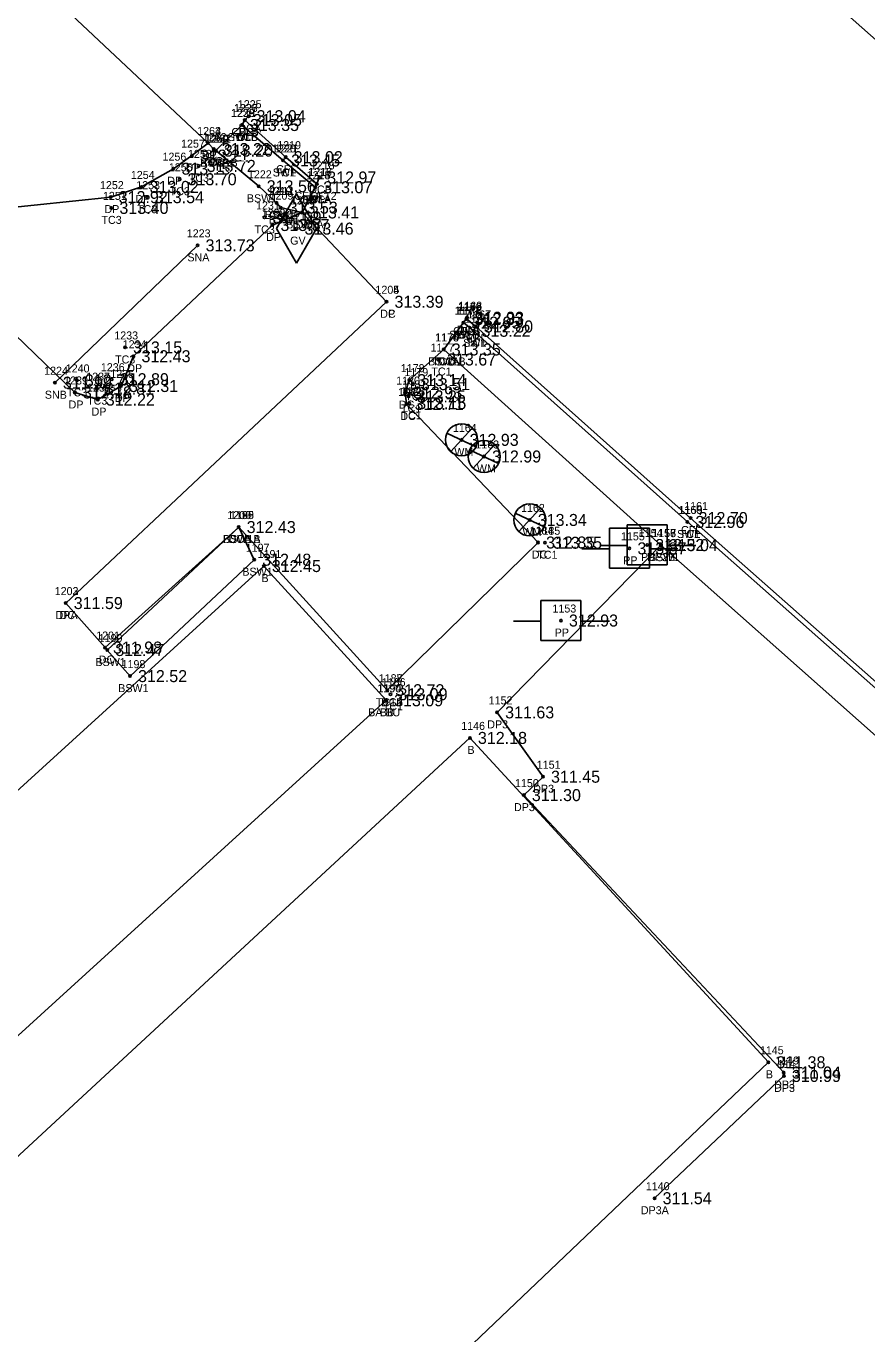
# Model space of a CAD drawing. Extents: x 1970076 to 1971136, y 803126 to 804215.
# Drawn here: x 1970736.9 to 1970842, y 803214.9 to 803378.3 of the extents above; entities that cross this region are included whole.
import ezdxf

# ---------------------------------------------------------------- set-up
doc = ezdxf.new("R2010")
doc.units = 0
for name, color, linetype in [('RD_EX_Bldg', 7, 'Continuous'), ('RD_EX_Bldg_txCode', 7, 'Continuous'), ('RD_EX_BldgApp', 7, 'Continuous'), ('RD_EX_BldgApp_txCode', 7, 'Continuous'), ('RD_EX_Conc', 7, 'Continuous'), ('RD_EX_Conc_txCode', 7, 'Continuous'), ('RD_EX_DR_Pipe', 7, 'Continuous'), ('RD_EX_Driveway', 7, 'Continuous'), ('RD_EX_Driveway_txCode', 7, 'Continuous'), ('RD_EX_TX_Bldg_ELEV', 7, 'Continuous'), ('RD_EX_TX_BldgApp_ELEV', 7, 'Continuous'), ('RD_EX_TX_Conc_ELEV', 7, 'Continuous'), ('RD_EX_TX_Driveway_ELEV', 7, 'Continuous'), ('RD_EX_TX_UT_ELEV', 7, 'Continuous'), ('RD_EX_UT', 7, 'Continuous'), ('RD_EX_UT_txCode', 7, 'Continuous'), ('RD_HC_Survey_ELEV', 7, 'Continuous'), ('RD_SMD_Locator', 7, 'Continuous')]:
    doc.layers.add(name, color=color, linetype=linetype)

msp = doc.modelspace()

# ---------------------------------------------------------------- linework, layer by layer
at = {"layer": 'RD_EX_Bldg'}
for points in [[(1970781.9, 803294.06), (1970766.62, 803310.84), (1970707.47, 803256.98), (1970722.75, 803240.2), (1970781.9, 803294.06)], [(1970698.2, 803132.22), (1970763.48, 803192.62), (1970767.27, 803189.39), (1970829.69, 803248.82), (1970792.38, 803289.36), (1970663.41, 803170.02), (1970698.2, 803132.22)]]:
    msp.add_lwpolyline(points, dxfattribs=at)
at = {"layer": 'RD_EX_BldgApp'}
msp.add_line((1970758.33, 803350.92), (1970740.49, 803333.75), dxfattribs=at)
at = {"layer": 'RD_EX_Conc'}
for points in [[(1970764.71, 803367.06), (1970764.24, 803366.58), (1970763.88, 803365.96), (1970760.62, 803362.76), (1970760.35, 803362.95), (1970759.65, 803363.71), (1970739.14, 803382.97), (1970738.49, 803383.57), (1970741.86, 803386.33), (1970742.28, 803386.82), (1970742.89, 803387.33)], [(1970773.04, 803358.18), (1970769.02, 803361.53), (1970763.88, 803365.96)], [(1970773.24, 803358.6), (1970769.35, 803361.94), (1970764.24, 803366.58)], [(1970771.39, 803355.03), (1970768.72, 803355.63), (1970768.22, 803356.23), (1970765.98, 803358.3), (1970760.62, 803362.76)], [(1970792.01, 803341.87), (1970791.95, 803341.72), (1970791.56, 803341.26), (1970789.11, 803337.91), (1970784.79, 803334.07), (1970784.27, 803332.52), (1970784.46, 803331.09), (1970800.9, 803313.78), (1970782.05, 803295.32), (1970763.47, 803315.71), (1970763.47, 803315.71), (1970746.76, 803300.65), (1970741.85, 803306.21), (1970781.95, 803343.87), (1970771.39, 803355.03), (1970773.04, 803358.18), (1970773.24, 803358.6), (1970773.54, 803359.4)], [(1970879.58, 803257.38), (1970880.21, 803258.23), (1970879.31, 803260.18), (1970872.53, 803269.28), (1970868.47, 803273.14), (1970819.57, 803316.35), (1970792.83, 803340.24), (1970791.56, 803341.26)], [(1970872.53, 803269.28), (1970872.62, 803269.6), (1970868.93, 803273.59), (1970819.97, 803316.84), (1970793.14, 803340.78), (1970791.95, 803341.72)], [(1970879.58, 803257.38), (1970878.06, 803258.86), (1970865.67, 803269.64), (1970816.24, 803313.45), (1970789.11, 803337.91)], [(1970763.47, 803315.71), (1970765.41, 803311.63), (1970749.89, 803297.08), (1970747.04, 803300.34), (1970763.47, 803315.71)]]:
    msp.add_lwpolyline(points, dxfattribs=at)
at = {"layer": 'RD_EX_DR_Pipe'}
msp.add_line((1971022.85, 803216.85), (1970817.34, 803399.52), dxfattribs=at)
at = {"layer": 'RD_EX_Driveway'}
for points in [[(1970741.85, 803306.21), (1970781.95, 803343.87), (1970771.39, 803355.03), (1970767.69, 803353.46), (1970750.32, 803337.06), (1970748.77, 803333.34), (1970745.86, 803331.64), (1970742.99, 803332.53), (1970726.64, 803348.27), (1970723.94, 803350.85), (1970724.44, 803353.41), (1970726.22, 803354.65), (1970728.27, 803354.93), (1970747.47, 803356.95), (1970751.34, 803358.22), (1970755.32, 803360.5), (1970757.62, 803362.13), (1970759.65, 803363.71), (1970739.14, 803382.97)], [(1970815.47, 803231.83), (1970831.63, 803247.11), (1970831.62, 803247.54), (1970799.12, 803282.21), (1970801.52, 803284.51), (1970795.78, 803292.55), (1970816.24, 803313.45)], [(1970853.81, 803200.3), (1970867.75, 803214.13), (1970871.37, 803240.87), (1970873.32, 803262.28), (1970865.32, 803269.32), (1970865.67, 803269.64), (1970816.24, 803313.45)]]:
    msp.add_lwpolyline(points, dxfattribs=at)
at = {"layer": 'RD_EX_UT'}
for p, q in [((1970768.2, 803353.01), (1970770.7, 803357.34)), ((1970770.7, 803357.34), (1970773.2, 803353.01)), ((1970768.2, 803353.01), (1970770.7, 803348.68)), ((1970770.7, 803348.68), (1970773.2, 803353.01)), ((1970789.99, 803325.15), (1970792.65, 803328.05)), ((1970789.51, 803327.45), (1970793.14, 803325.74)), ((1970792.32, 803325.37), (1970795.95, 803323.65)), ((1970792.8, 803323.07), (1970795.47, 803325.97)), ((1970798.51, 803315.14), (1970801.17, 803318.03)), ((1970798.03, 803317.43), (1970801.66, 803315.72)), ((1970814.82, 803315.56), (1970809.82, 803315.56)), ((1970809.82, 803315.56), (1970809.82, 803310.56)), ((1970817.04, 803315.98), (1970812.04, 803315.98)), ((1970812.04, 803315.98), (1970812.04, 803310.98)), ((1970814.82, 803310.56), (1970814.82, 803315.56)), ((1970817.04, 803310.98), (1970817.04, 803315.98)), ((1970806.38, 803313), (1970809.85, 803313)), ((1970808.61, 803313.42), (1970812.08, 803313.42)), ((1970814.74, 803313), (1970818.38, 803313)), ((1970816.97, 803313.42), (1970820.61, 803313.42)), ((1970809.82, 803310.56), (1970814.82, 803310.56)), ((1970812.04, 803310.98), (1970817.04, 803310.98)), ((1970806.25, 803306.53), (1970801.25, 803306.53)), ((1970801.25, 803306.53), (1970801.25, 803301.53)), ((1970806.25, 803301.53), (1970806.25, 803306.53)), ((1970797.82, 803303.97), (1970801.29, 803303.97)), ((1970806.18, 803303.97), (1970809.82, 803303.97)), ((1970801.25, 803301.53), (1970806.25, 803301.53))]:
    msp.add_line(p, q, dxfattribs=at)
for centre in [(1970791.34, 803326.61), (1970794.15, 803324.53), (1970799.86, 803316.6)]:
    msp.add_circle(centre, 2, dxfattribs=at)
at = {"layer": 'RD_SMD_Locator'}
for centre in [(1970764.71, 803367.06), (1970763.88, 803365.96), (1970763.88, 803365.96), (1970763.88, 803365.96), (1970764.24, 803366.58), (1970764.24, 803366.58), (1970759.65, 803363.71), (1970759.65, 803363.71), (1970757.62, 803362.13), (1970760.35, 803362.95), (1970760.62, 803362.76), (1970760.62, 803362.76), (1970760.62, 803362.76), (1970769.35, 803361.94), (1970755.32, 803360.5), (1970758.47, 803360.85), (1970769.02, 803361.53), (1970769.02, 803361.53), (1970756.08, 803359.18), (1970773.54, 803359.4), (1970751.34, 803358.22), (1970765.98, 803358.3), (1970773.04, 803358.18), (1970773.04, 803358.18), (1970773.04, 803358.18), (1970773.24, 803358.6), (1970773.24, 803358.6), (1970747.47, 803356.95), (1970747.56, 803355.6), (1970752, 803356.94), (1970768.22, 803356.23), (1970768.22, 803356.23), (1970768.72, 803355.63), (1970766.7, 803354.41), (1970771.39, 803355.03), (1970771.39, 803355.03), (1970771.39, 803355.03), (1970767.69, 803353.46), (1970770.7, 803353.01), (1970758.33, 803350.92), (1970781.95, 803343.87), (1970781.95, 803343.87), (1970791.56, 803341.26), (1970791.56, 803341.26), (1970791.56, 803341.26), (1970791.95, 803341.72), (1970791.95, 803341.72), (1970792.01, 803341.87), (1970793.14, 803340.78), (1970792.83, 803340.24), (1970792.83, 803340.24), (1970749.27, 803338.16), (1970789.11, 803337.91), (1970789.11, 803337.91), (1970789.11, 803337.91), (1970750.32, 803337.06), (1970788.52, 803336.65), (1970747.61, 803334.19), (1970740.49, 803333.75), (1970742.99, 803332.53), (1970743.24, 803334.04), (1970745.76, 803333.01), (1970748.77, 803333.34), (1970784.27, 803332.52), (1970784.79, 803334.07), (1970785.25, 803333.57), (1970745.86, 803331.64), (1970784.46, 803331.09), (1970784.73, 803332.04), (1970784.79, 803331.19), (1970791.34, 803326.61), (1970794.15, 803324.53), (1970799.86, 803316.6), (1970819.57, 803316.35), (1970819.57, 803316.35), (1970819.97, 803316.84), (1970763.47, 803315.71), (1970763.47, 803315.71), (1970763.47, 803315.71), (1970763.47, 803315.71), (1970800.9, 803313.78), (1970801.76, 803313.75), (1970812.32, 803313.05), (1970814.55, 803313.47), (1970816.24, 803313.45), (1970816.24, 803313.45), (1970816.24, 803313.45), (1970765.41, 803311.63), (1970766.62, 803310.84), (1970741.85, 803306.21), (1970741.85, 803306.21), (1970803.76, 803304.03), (1970746.76, 803300.65), (1970747.04, 803300.34), (1970749.89, 803297.08), (1970782.05, 803295.32), (1970782.05, 803295.32), (1970781.9, 803294.06), (1970781.9, 803294.06), (1970782.45, 803294.82), (1970795.78, 803292.55), (1970792.38, 803289.36), (1970801.52, 803284.51), (1970799.12, 803282.21), (1970829.69, 803248.82), (1970831.62, 803247.54), (1970831.63, 803247.11), (1970815.47, 803231.83)]:
    msp.add_circle(centre, 0.15, dxfattribs=at)

# ---------------------------------------------------------------- texts
at = {"layer": 'RD_EX_Bldg_txCode'}
for s, p in [('1191', (1970765.84, 803311.84)), ('B', (1970766.32, 803308.84)), ('1190', (1970780.8, 803295.06)), ('1194', (1970780.84, 803295.06)), ('BA BU', (1970779.66, 803292.06)), ('BB', (1970781.12, 803292.06)), ('1146', (1970791.29, 803290.36)), ('B', (1970792.07, 803287.36)), ('1145', (1970828.63, 803249.82)), ('B', (1970829.38, 803246.82))]:
    msp.add_text(s, height=1, dxfattribs=at).set_placement(p)
at = {"layer": 'RD_EX_BldgApp_txCode'}
for s, p in [('1223', (1970756.98, 803351.92)), ('SNA', (1970757.06, 803348.92)), ('1224', (1970739.15, 803334.75)), ('SNB', (1970739.24, 803331.75))]:
    msp.add_text(s, height=1, dxfattribs=at).set_placement(p)
at = {"layer": 'RD_EX_Conc_txCode'}
for s, p in [('1226', (1970762.87, 803367.58)), ('1227', (1970762.9, 803367.58)), ('1225', (1970763.36, 803368.06)), ('1230', (1970762.49, 803366.96)), ('1228', (1970762.53, 803366.96)), ('1229', (1970762.53, 803366.96)), ('1264', (1970758.28, 803364.71)), ('CFLB', (1970762.56, 803364.58)), ('DCA', (1970763.44, 803365.06)), ('DC', (1970763.46, 803364.58)), ('1262', (1970758.98, 803363.95)), ('1260', (1970759.21, 803363.76)), ('1259', (1970759.27, 803363.76)), ('1261', (1970759.53, 803363.76)), ('SWLB', (1970762.11, 803363.96)), ('TC1B', (1970762.45, 803363.96)), ('DC', (1970763.1, 803363.96)), ('1219', (1970768.29, 803362.94)), ('1258', (1970757.13, 803361.85)), ('DC', (1970758.87, 803361.71)), ('1220', (1970767.64, 803362.53)), ('1221', (1970767.96, 803362.53)), ('1255', (1970754.74, 803360.18)), ('BSW1B', (1970758.67, 803360.76)), ('TC3B', (1970758.9, 803360.76)), ('DC', (1970759.57, 803360.95)), ('DC', (1970759.84, 803360.76)), ('SWL', (1970767.73, 803359.53)), ('TC1', (1970768.06, 803359.53)), ('CFL', (1970768.15, 803359.94)), ('1216', (1970772.15, 803359.6)), ('1217', (1970772.18, 803359.6)), ('1218', (1970772.47, 803360.4)), ('1253', (1970750.66, 803357.94)), ('TC3', (1970757.23, 803358.85)), ('1222', (1970764.63, 803359.3)), ('1213', (1970771.97, 803359.18)), ('1214', (1970771.97, 803359.18)), ('1215', (1970771.97, 803359.18)), ('1251', (1970746.5, 803356.6)), ('TC3', (1970754.84, 803357.18)), ('BSW1', (1970764.5, 803356.3)), ('1210', (1970767.11, 803357.23)), ('1209', (1970767.33, 803356.63)), ('1211', (1970767.44, 803357.23)), ('CFLA 12', (1970770.44, 803356.6)), ('SWLA', (1970771.26, 803356.18)), ('TC1A', (1970771.59, 803356.18)), ('DC', (1970772.26, 803356.18)), ('DCB', (1970772.29, 803357.4)), ('DC', (1970772.46, 803356.6)), ('TC3', (1970750.76, 803354.94)), ('1231', (1970765.64, 803355.41)), ('1207', (1970770.01, 803356.03)), ('1208', (1970770.01, 803356.03)), ('TC3', (1970746.32, 803353.6)), ('TC3A', (1970766.48, 803354.23)), ('BSW1', (1970766.74, 803354.23)), ('BSW1', (1970767.24, 803353.63)), ('BSW1A', (1970769.42, 803353.03)), ('DC', (1970770.61, 803353.03)), ('TC3', (1970765.46, 803352.41)), ('1205', (1970780.57, 803344.87)), ('DC', (1970781.17, 803341.87)), ('1170', (1970790.46, 803342.26)), ('1172', (1970790.5, 803342.26)), ('1171', (1970790.78, 803342.26)), ('1169', (1970790.87, 803342.72)), ('1173', (1970790.89, 803342.72)), ('1168', (1970790.93, 803342.87)), ('1167', (1970792.05, 803341.78)), ('DCA', (1970790.75, 803339.87)), ('1166', (1970791.72, 803341.24)), ('1165', (1970791.74, 803341.24)), ('1233', (1970747.92, 803339.16)), ('1176', (1970788.03, 803338.91)), ('1174', (1970788.05, 803338.91)), ('1175', (1970788.05, 803338.91)), ('SWLB', (1970789.8, 803339.26)), ('TC1B', (1970790.13, 803339.26)), ('CFLB', (1970790.28, 803339.72)), ('DC', (1970790.78, 803339.26)), ('DC', (1970791.17, 803339.72)), ('SWL', (1970791.54, 803338.24)), ('TC1', (1970791.87, 803338.24)), ('CFL', (1970791.93, 803338.78)), ('1177', (1970787.46, 803337.65)), ('1240', (1970741.85, 803335.04)), ('1236', (1970746.24, 803335.19)), ('TC3', (1970748.02, 803336.16)), ('1178', (1970783.73, 803335.07)), ('BSW1B', (1970787.16, 803335.91)), ('TC1A', (1970787.66, 803335.91)), ('DC', (1970788.33, 803335.91)), ('1237', (1970744.41, 803334.01)), ('1180', (1970783.16, 803333.52)), ('1179', (1970784.19, 803334.57)), ('TC1', (1970787.56, 803334.65)), ('TC3', (1970742, 803332.04)), ('TC3', (1970746.36, 803332.19)), ('1182', (1970783.4, 803332.09)), ('1183', (1970783.73, 803332.19)), ('1181', (1970783.95, 803333.04)), ('DC', (1970784.01, 803332.07)), ('TC3', (1970744.52, 803331.01)), ('DC', (1970783.49, 803330.52)), ('TC1', (1970783.77, 803330.04)), ('TC1', (1970784.29, 803331.57)), ('DC', (1970783.68, 803329.09)), ('TC1', (1970783.83, 803329.19)), ('1160', (1970818.44, 803317.35)), ('1159', (1970818.5, 803317.35)), ('1161', (1970819.17, 803317.84)), ('1200', (1970762.05, 803316.71)), ('1196', (1970762.39, 803316.71)), ('1189', (1970762.41, 803316.71)), ('1195', (1970762.41, 803316.71)), ('BSW1A', (1970761.5, 803313.71)), ('BSW1B', (1970761.52, 803313.71)), ('DCA', (1970762.2, 803313.71)), ('DCB', (1970762.22, 803313.71)), ('1184', (1970799.84, 803314.78)), ('1185', (1970800.7, 803314.75)), ('1157', (1970815.18, 803314.45)), ('SWL', (1970818.27, 803314.35)), ('TC1', (1970818.61, 803314.35)), ('CFL', (1970818.77, 803314.84)), ('1197', (1970764.35, 803312.63)), ('DC', (1970800.12, 803311.78)), ('TC1', (1970800.8, 803311.75)), ('BSW1', (1970814.76, 803311.45)), ('BSW1', (1970763.93, 803309.63)), ('1202', (1970740.47, 803307.21)), ('DC', (1970741.07, 803304.21)), ('1201', (1970745.66, 803301.65)), ('1199', (1970745.97, 803301.34)), ('BSW1', (1970745.56, 803298.34)), ('DC', (1970745.98, 803298.65)), ('1198', (1970748.83, 803298.08)), ('1187', (1970780.98, 803296.32)), ('1188', (1970780.98, 803296.32)), ('1186', (1970781.36, 803295.82)), ('BSW1', (1970748.41, 803295.08)), ('TC1B', (1970780.61, 803293.32)), ('DC', (1970781.27, 803293.32)), ('TC1', (1970781.49, 803292.82))]:
    msp.add_text(s, height=1, dxfattribs=at).set_placement(p)
at = {"layer": 'RD_EX_Driveway_txCode'}
for s, p in [('1263', (1970758.28, 803364.71)), ('1257', (1970756.27, 803363.13)), ('1256', (1970753.95, 803361.5)), ('DP', (1970758.87, 803361.71)), ('DP', (1970756.84, 803360.13)), ('1252', (1970746.13, 803357.95)), ('1254', (1970749.99, 803359.22)), ('DP', (1970754.54, 803358.5)), ('DP', (1970750.56, 803356.22)), ('DP', (1970746.69, 803354.95)), ('1206', (1970769.98, 803356.03)), ('1232', (1970766.34, 803354.46)), ('DP', (1970770.61, 803353.03)), ('DP', (1970766.91, 803351.46)), ('1204', (1970780.57, 803344.87)), ('DP', (1970781.17, 803341.87)), ('1234', (1970748.97, 803338.06)), ('DP', (1970749.54, 803335.06)), ('1239', (1970741.65, 803333.53)), ('1235', (1970747.42, 803334.34)), ('1238', (1970744.51, 803332.64)), ('DP', (1970742.21, 803330.53)), ('DP', (1970747.99, 803331.34)), ('DP', (1970745.08, 803329.64)), ('1156', (1970815.16, 803314.45)), ('1158', (1970815.18, 803314.45)), ('DP3B', (1970814.54, 803311.45)), ('DP2B', (1970814.54, 803311.45)), ('1203', (1970740.47, 803307.21)), ('DPA', (1970740.58, 803304.21)), ('1152', (1970794.72, 803293.55)), ('DP3', (1970794.55, 803290.55)), ('1151', (1970800.74, 803285.51)), ('1150', (1970798.01, 803283.21)), ('DP3', (1970800.29, 803282.51)), ('DP3', (1970797.89, 803280.21)), ('1149', (1970830.56, 803248.54)), ('1141', (1970830.85, 803248.11)), ('DP3', (1970830.4, 803245.54)), ('DP3', (1970830.41, 803245.11)), ('1140', (1970814.37, 803232.83)), ('DP3A', (1970813.75, 803229.83))]:
    msp.add_text(s, height=1, dxfattribs=at).set_placement(p)
at = {"layer": 'RD_EX_TX_Bldg_ELEV'}
for s, p in [('312.45', (1970767.62, 803310.09)), ('313.09', (1970782.9, 803293.31)), ('313.09', (1970782.9, 803293.31)), ('312.18', (1970793.38, 803288.61)), ('311.38', (1970830.69, 803248.07))]:
    msp.add_text(s, height=1.5, dxfattribs=at).set_placement(p)
at = {"layer": 'RD_EX_TX_BldgApp_ELEV'}
for s, p in [('313.73', (1970759.33, 803350.17)), ('311.99', (1970741.49, 803333))]:
    msp.add_text(s, height=1.5, dxfattribs=at).set_placement(p)
at = {"layer": 'RD_EX_TX_Conc_ELEV'}
for s, p in [('313.05', (1970765.24, 803365.83)), ('313.05', (1970765.24, 803365.83)), ('313.04', (1970765.71, 803366.31)), ('313.35', (1970764.88, 803365.21)), ('313.35', (1970764.88, 803365.21)), ('313.35', (1970764.88, 803365.21)), ('313.22', (1970760.65, 803362.96)), ('313.22', (1970761.35, 803362.2)), ('313.20', (1970761.62, 803362.01)), ('313.20', (1970761.62, 803362.01)), ('313.20', (1970761.62, 803362.01)), ('313.45', (1970770.02, 803360.78)), ('313.45', (1970770.02, 803360.78)), ('313.02', (1970770.35, 803361.19)), ('313.72', (1970759.47, 803360.1)), ('313.70', (1970757.08, 803358.43)), ('313.56', (1970766.98, 803357.55)), ('313.07', (1970774.04, 803357.43)), ('313.07', (1970774.04, 803357.43)), ('313.07', (1970774.04, 803357.43)), ('313.02', (1970774.24, 803357.85)), ('313.02', (1970774.24, 803357.85)), ('312.97', (1970774.54, 803358.65)), ('313.54', (1970753, 803356.19)), ('313.40', (1970748.56, 803354.85)), ('313.51', (1970769.22, 803355.48)), ('313.51', (1970769.22, 803355.48)), ('313.53', (1970769.72, 803354.88)), ('313.41', (1970772.39, 803354.28)), ('313.41', (1970772.39, 803354.28)), ('314.09', (1970767.7, 803353.66)), ('313.39', (1970782.95, 803343.12)), ('312.83', (1970792.95, 803340.97)), ('312.83', (1970792.95, 803340.97)), ('312.93', (1970793.01, 803341.12)), ('312.95', (1970792.56, 803340.51)), ('312.95', (1970792.56, 803340.51)), ('312.95', (1970792.56, 803340.51)), ('313.22', (1970793.83, 803339.49)), ('313.22', (1970793.83, 803339.49)), ('312.80', (1970794.14, 803340.03)), ('313.15', (1970750.27, 803337.41)), ('313.35', (1970790.11, 803337.16)), ('313.35', (1970790.11, 803337.16)), ('313.35', (1970790.11, 803337.16)), ('313.67', (1970789.52, 803335.9)), ('312.70', (1970744.24, 803333.29)), ('312.89', (1970748.61, 803333.44)), ('313.14', (1970785.79, 803333.32)), ('313.51', (1970786.25, 803332.82)), ('312.81', (1970746.76, 803332.26)), ('312.93', (1970785.27, 803331.77)), ('313.25', (1970785.73, 803331.29)), ('312.71', (1970785.46, 803330.34)), ('313.15', (1970785.79, 803330.44)), ('312.43', (1970764.47, 803314.96)), ('312.43', (1970764.47, 803314.96)), ('312.43', (1970764.47, 803314.96)), ('312.43', (1970764.47, 803314.96)), ('312.96', (1970820.57, 803315.6)), ('312.96', (1970820.57, 803315.6)), ('312.70', (1970820.97, 803316.09)), ('312.85', (1970801.9, 803313.03)), ('313.35', (1970802.76, 803313)), ('313.04', (1970817.24, 803312.7)), ('312.48', (1970766.41, 803310.88)), ('311.59', (1970742.85, 803305.46)), ('311.98', (1970747.76, 803299.9)), ('312.47', (1970748.04, 803299.59)), ('312.52', (1970750.89, 803296.33)), ('312.72', (1970783.05, 803294.57)), ('312.72', (1970783.05, 803294.57)), ('313.09', (1970783.45, 803294.07))]:
    msp.add_text(s, height=1.5, dxfattribs=at).set_placement(p)
at = {"layer": 'RD_EX_TX_Driveway_ELEV'}
for s, p in [('313.22', (1970760.65, 803362.96)), ('313.21', (1970758.62, 803361.38)), ('313.15', (1970756.32, 803359.75)), ('313.02', (1970752.34, 803357.47)), ('312.92', (1970748.47, 803356.2)), ('313.41', (1970772.39, 803354.28)), ('313.57', (1970768.69, 803352.71)), ('313.39', (1970782.95, 803343.12)), ('312.43', (1970751.32, 803336.31)), ('312.18', (1970743.99, 803331.78)), ('312.31', (1970749.77, 803332.59)), ('312.22', (1970746.86, 803330.89)), ('313.04', (1970817.24, 803312.7)), ('313.04', (1970817.24, 803312.7)), ('311.59', (1970742.85, 803305.46)), ('311.63', (1970796.78, 803291.8)), ('311.45', (1970802.52, 803283.76)), ('311.30', (1970800.12, 803281.46)), ('311.04', (1970832.62, 803246.79)), ('310.99', (1970832.63, 803246.36)), ('311.54', (1970816.47, 803231.08))]:
    msp.add_text(s, height=1.5, dxfattribs=at).set_placement(p)
at = {"layer": 'RD_EX_TX_UT_ELEV'}
for s, p in [('313.46', (1970771.7, 803352.26)), ('312.93', (1970792.34, 803325.86)), ('312.99', (1970795.15, 803323.78)), ('313.34', (1970800.86, 803315.85))]:
    msp.add_text(s, height=1.5, dxfattribs=at).set_placement(p)
at = {"layer": 'RD_EX_UT_txCode'}
for s, p in [('1212', (1970769.64, 803354.01)), ('GV', (1970769.91, 803351.01)), ('1164', (1970790.25, 803327.61)), ('1163', (1970793.06, 803325.53)), ('WM', (1970790.43, 803324.61)), ('WM', (1970793.25, 803322.53)), ('1162', (1970798.77, 803317.6)), ('WM', (1970798.95, 803314.6)), ('1155', (1970811.26, 803314.05)), ('1154', (1970813.49, 803314.47)), ('PP', (1970811.54, 803311.05)), ('PP', (1970813.77, 803311.47)), ('1153', (1970802.7, 803305.03)), ('PP', (1970802.98, 803302.03))]:
    msp.add_text(s, height=1, dxfattribs=at).set_placement(p)
at = {"layer": 'RD_HC_Survey_ELEV'}
for s, p in [('313.87', (1970813.32, 803312.3)), ('313.52', (1970815.55, 803312.72)), ('312.93', (1970804.76, 803303.28))]:
    msp.add_text(s, height=1.5, dxfattribs=at).set_placement(p)

doc.saveas('drawing.dxf')
